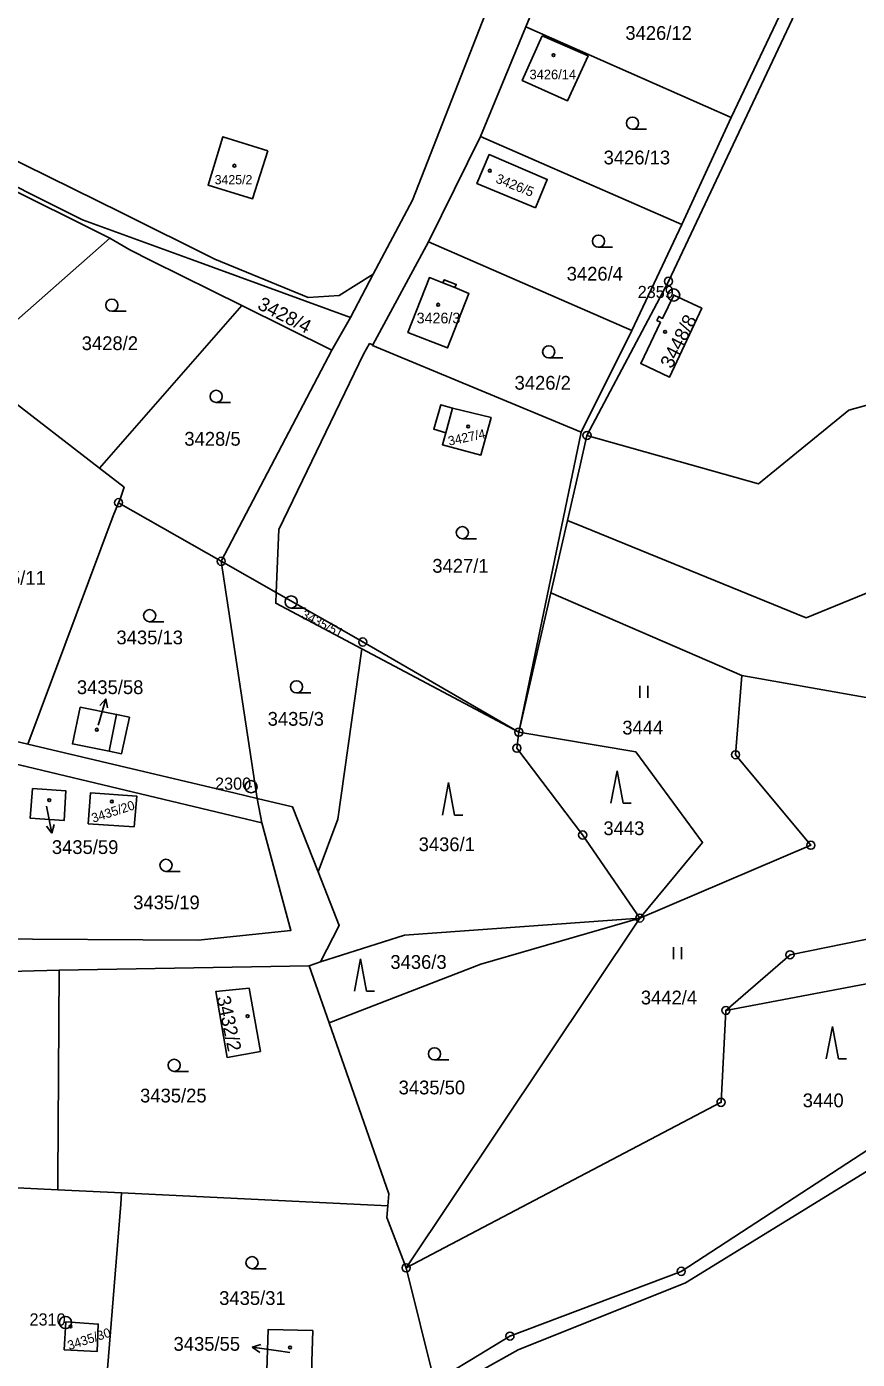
# Model space of a CAD drawing. Extents: x -644096 to -634268, y -1141430 to -1133463.
# Drawn here: x -641809.5 to -641706.9, y -1138397.7 to -1138233.1 of the extents above; entities that cross this region are included whole.
import ezdxf

# ---------------------------------------------------------------- set-up
doc = ezdxf.new("R2010")
doc.units = 0
for name, color, linetype in [('_CIVIL_CONSTRUCTION', 7, 'Continuous'), ('M_Svah_Nasyp', 7, 'Continuous'), ('M_Svah_Zarez', 7, 'Continuous'), ('svrsek_osa_sjezdy', 7, 'Continuous'), ('svrsek_osa_VRT', 7, 'Continuous'), ('svrsek_popisy_VRT', 7, 'Continuous'), ('terminal_VRT', 7, 'Continuous')]:
    doc.layers.add(name, color=color, linetype=linetype)

msp = doc.modelspace()

# ---------------------------------------------------------------- linework, layer by layer
at = {"layer": '_CIVIL_CONSTRUCTION'}
for centre, radius in [((-641730.21, -1138264.55), 0.5), ((-641729.57, -1138266.24), 0.75), ((-641730.21, -1138264.55), 0.0303), ((-641729.57, -1138266.24), 0.03), ((-641740.28, -1138283.58), 0.5), ((-641740.28, -1138283.58), 0.0303), ((-641798.15, -1138291.89), 0.5), ((-641798.15, -1138291.89), 0.0303), ((-641785.47, -1138299.13), 0.5), ((-641785.47, -1138299.13), 0.0303), ((-641767.98, -1138309.09), 0.5), ((-641767.98, -1138309.09), 0.0303), ((-641748.7, -1138320.23), 0.5), ((-641748.7, -1138320.23), 0.0303), ((-641748.94, -1138322.21), 0.5), ((-641748.94, -1138322.21), 0.0303), ((-641721.93, -1138323.02), 0.5), ((-641721.93, -1138323.02), 0.0303), ((-641781.78, -1138326.97), 0.75), ((-641781.78, -1138326.97), 0.03), ((-641740.82, -1138332.93), 0.5), ((-641740.82, -1138332.93), 0.0303), ((-641712.63, -1138334.2), 0.5), ((-641712.63, -1138334.2), 0.0303), ((-641733.76, -1138343.2), 0.5), ((-641733.76, -1138343.2), 0.0303), ((-641715.2, -1138347.73), 0.5), ((-641715.2, -1138347.73), 0.0303), ((-641723.12, -1138354.6), 0.5), ((-641723.12, -1138354.6), 0.0303), ((-641723.72, -1138365.95), 0.5), ((-641723.72, -1138365.95), 0.0303), ((-641762.62, -1138386.4), 0.5), ((-641762.62, -1138386.4), 0.0303), ((-641728.64, -1138386.83), 0.5), ((-641728.64, -1138386.83), 0.0303), ((-641804.7, -1138393.14), 0.75), ((-641804.7, -1138393.14), 0.03), ((-641749.8, -1138394.83), 0.5), ((-641749.8, -1138394.83), 0.0303)]:
    msp.add_circle(centre, radius, dxfattribs=at)
at = {"layer": 'M_Svah_Nasyp'}
for p, q in [((-641758.1, -1138264.74), (-641756.61, -1138265.32)), ((-641757.72, -1138283.24), (-641756.88, -1138280.2)), ((-641798.4, -1138318.04), (-641799.29, -1138322.58))]:
    msp.add_line(p, q, dxfattribs=at)
at = {"layer": 'M_Svah_Zarez'}
for centre in [(-641744.41, -1138236.61), (-641783.84, -1138250.27), (-641752.28, -1138250.88), (-641758.67, -1138267.43), (-641730.64, -1138270.78), (-641754.97, -1138282.47), (-641800.84, -1138319.93), (-641806.71, -1138328.63), (-641798.98, -1138328.8), (-641782.21, -1138355.31), (-641804.09, -1138393.64), (-641776.97, -1138396.23)]:
    msp.add_circle(centre, 0.175, dxfattribs=at)
at = {"layer": 'svrsek_osa_sjezdy'}
for p, q in [((-641734.66, -1138245.76), (-641732.91, -1138245.76)), ((-641738.86, -1138260.34), (-641737.11, -1138260.34)), ((-641798.98, -1138268.25), (-641797.23, -1138268.25)), ((-641745.01, -1138274.01), (-641743.26, -1138274.01)), ((-641786.08, -1138279.51), (-641784.33, -1138279.51)), ((-641755.68, -1138296.34), (-641753.93, -1138296.34)), ((-641776.82, -1138304.9), (-641775.07, -1138304.9)), ((-641794.31, -1138306.59), (-641792.56, -1138306.59)), ((-641733.75, -1138316), (-641733.75, -1138314.5)), ((-641732.75, -1138316), (-641732.75, -1138314.5)), ((-641776.16, -1138315.38), (-641774.41, -1138315.38)), ((-641757.38, -1138326.47), (-641758.13, -1138330.47)), ((-641756.63, -1138330.47), (-641757.38, -1138326.47)), ((-641736.57, -1138325.02), (-641737.32, -1138329.02)), ((-641735.82, -1138329.02), (-641736.57, -1138325.02)), ((-641735.82, -1138329.02), (-641734.82, -1138329.02)), ((-641756.63, -1138330.47), (-641755.63, -1138330.47)), ((-641792.29, -1138337.43), (-641790.54, -1138337.43)), ((-641729.6, -1138348.27), (-641729.6, -1138346.77)), ((-641728.6, -1138348.27), (-641728.6, -1138346.77)), ((-641768.27, -1138348.23), (-641769.02, -1138352.23)), ((-641767.52, -1138352.23), (-641768.27, -1138348.23)), ((-641767.52, -1138352.23), (-641766.52, -1138352.23)), ((-641709.97, -1138356.57), (-641710.72, -1138360.57)), ((-641709.22, -1138360.57), (-641709.97, -1138356.57)), ((-641759.11, -1138360.72), (-641757.36, -1138360.72)), ((-641709.22, -1138360.57), (-641708.22, -1138360.57)), ((-641791.27, -1138362.13), (-641789.52, -1138362.13)), ((-641781.66, -1138386.51), (-641779.91, -1138386.51))]:
    msp.add_line(p, q, dxfattribs=at)
for centre in [(-641734.66, -1138245.01), (-641738.86, -1138259.59), (-641798.98, -1138267.5), (-641745.01, -1138273.26), (-641786.08, -1138278.76), (-641755.68, -1138295.59), (-641776.82, -1138304.15), (-641794.31, -1138305.84), (-641776.16, -1138314.63), (-641792.29, -1138336.68), (-641759.11, -1138359.97), (-641791.27, -1138361.38), (-641781.66, -1138385.76)]:
    msp.add_circle(centre, 0.75, dxfattribs=at)
at = {"layer": 'svrsek_popisy_VRT'}
for p, q in [((-641800.55, -1138319), (-641799.72, -1138316.11)), ((-641799.72, -1138316.11), (-641800.48, -1138316.94)), ((-641799.72, -1138316.11), (-641799.52, -1138317.22)), ((-641800.65, -1138319.36), (-641800.55, -1138319)), ((-641807.04, -1138329.37), (-641806.96, -1138329.77)), ((-641806.96, -1138329.77), (-641806.39, -1138332.72)), ((-641806.39, -1138332.72), (-641807.07, -1138331.83)), ((-641806.39, -1138332.72), (-641806.09, -1138331.64)), ((-641781.63, -1138396.2), (-641780.57, -1138395.85)), ((-641778.66, -1138396.62), (-641781.63, -1138396.2)), ((-641781.63, -1138396.2), (-641780.71, -1138396.84)), ((-641777, -1138396.86), (-641778.66, -1138396.62))]:
    msp.add_line(p, q, dxfattribs=at)
at = {"layer": 'terminal_VRT'}
for p, q in [((-641742.57, -1138220.27), (-641747.83, -1138233.12)), ((-641716.51, -1138231.76), (-641722.46, -1138244.32)), ((-641747.83, -1138233.12), (-641753.43, -1138246.65)), ((-641747.83, -1138233.12), (-641722.46, -1138244.32)), ((-641722.46, -1138244.32), (-641728.56, -1138257.54)), ((-641753.43, -1138246.65), (-641759.87, -1138259.65)), ((-641728.56, -1138257.54), (-641753.43, -1138246.65)), ((-641799.24, -1138259.2), (-641818.53, -1138249.61)), ((-641728.56, -1138257.54), (-641734.75, -1138270.6)), ((-641817.73, -1138275.54), (-641799.24, -1138259.2)), ((-641759.87, -1138259.65), (-641766.74, -1138272.4)), ((-641734.75, -1138270.6), (-641759.87, -1138259.65)), ((-641769.51, -1138269.01), (-641766.68, -1138263.67)), ((-641800.52, -1138287.62), (-641782.94, -1138267.52)), ((-641782.94, -1138267.52), (-641771.82, -1138273.05)), ((-641771.82, -1138273.05), (-641769.51, -1138269.01)), ((-641734.75, -1138270.6), (-641741, -1138283.17)), ((-641785.47, -1138299.13), (-641771.82, -1138273.05)), ((-641812.34, -1138278.47), (-641800.52, -1138287.62)), ((-641741, -1138283.17), (-641748.7, -1138320.23)), ((-641798.15, -1138291.89), (-641785.47, -1138299.13)), ((-641744.75, -1138303.02), (-641742.69, -1138294.07)), ((-641778.68, -1138303), (-641785.47, -1138299.13)), ((-641748.7, -1138320.23), (-641744.75, -1138303.02)), ((-641721.15, -1138313.25), (-641744.75, -1138303.02)), ((-641768.1, -1138309.94), (-641748.7, -1138320.23)), ((-641809.37, -1138321.7), (-641827.1, -1138317.49)), ((-641815.38, -1138323.1), (-641780.43, -1138331.43)), ((-641781.03, -1138328.43), (-641780.43, -1138331.43)), ((-641762.62, -1138386.4), (-641733.76, -1138343.2)), ((-641805.49, -1138349.64), (-641774.62, -1138349.08)), ((-641774.62, -1138349.08), (-641773.19, -1138348.62)), ((-641772.15, -1138356.15), (-641774.62, -1138349.08)), ((-641841.15, -1138350.6), (-641805.49, -1138349.64)), ((-641828.21, -1138375.66), (-641805.66, -1138376.75)), ((-641805.66, -1138376.75), (-641797.77, -1138377.13)), ((-641797.77, -1138377.13), (-641764.9, -1138378.72)), ((-641759.13, -1138400.46), (-641762.62, -1138386.4))]:
    msp.add_line(p, q, dxfattribs=at)
for points in [[(-641740.9, -1138201.05), (-641761.83, -1138254.53), (-641766.68, -1138263.67)], [(-641701.01, -1138202.68), (-641730.21, -1138264.55), (-641740.28, -1138283.58)], [(-641745.81, -1138234.21), (-641740.15, -1138236.71), (-641742.67, -1138242.24), (-641748.27, -1138239.76), (-641745.81, -1138234.21)], [(-641766.68, -1138263.67), (-641770.88, -1138266.3), (-641774.72, -1138266.53), (-641786.27, -1138261.82), (-641797.74, -1138256.08), (-641830.92, -1138239.73), (-641832.34, -1138239.03), (-641834.87, -1138239.21)], [(-641833.06, -1138243.41), (-641831.7, -1138242.36), (-641802.61, -1138256.95), (-641789.02, -1138261.91), (-641769.51, -1138269.01)], [(-641779.7, -1138248.41), (-641785.26, -1138246.68), (-641787.1, -1138252.66), (-641781.6, -1138254.35), (-641779.7, -1138248.41)], [(-641746.66, -1138255.48), (-641753.87, -1138252.48), (-641752.38, -1138248.9), (-641745.19, -1138251.95), (-641746.66, -1138255.48)], [(-641782.94, -1138267.52), (-641794.06, -1138262), (-641796.75, -1138260.67), (-641799.24, -1138259.2)], [(-641740.28, -1138283.58), (-641719.09, -1138289.56), (-641707.92, -1138280.44), (-641699.75, -1138278.19), (-641686.23, -1138278.71), (-641672.58, -1138275.91), (-641665.73, -1138268.46), (-641654.72, -1138262.46), (-641643.02, -1138262.72)], [(-641758.1, -1138264.74), (-641757.91, -1138264.35), (-641756.44, -1138264.92), (-641756.61, -1138265.32), (-641754.87, -1138266.03), (-641757.52, -1138272.78), (-641762.4, -1138270.86), (-641759.74, -1138264.09), (-641758.1, -1138264.74)], [(-641731.18, -1138269.59), (-641733.63, -1138274.69), (-641730.1, -1138276.4), (-641726.11, -1138267.87), (-641729.57, -1138266.24), (-641730.95, -1138269.12), (-641731.42, -1138268.89), (-641731.65, -1138269.37), (-641731.18, -1138269.59)], [(-641638.73, -1138268.6), (-641651.7, -1138278), (-641667.04, -1138291.3), (-641687.63, -1138295.65), (-641713.2, -1138306.13), (-641740.75, -1138294.86), (-641742.69, -1138294.07)], [(-641778.68, -1138303), (-641778.33, -1138295.18), (-641767.89, -1138273.55), (-641767.14, -1138272.23), (-641766.74, -1138272.4)], [(-641766.74, -1138272.4), (-641766.79, -1138272.49), (-641741, -1138283.17)], [(-641757.72, -1138283.24), (-641759.22, -1138282.82), (-641758.33, -1138279.8), (-641756.88, -1138280.2), (-641752.12, -1138281.37), (-641753.39, -1138286), (-641758.14, -1138284.74), (-641757.72, -1138283.24)], [(-641742.69, -1138294.07), (-641741.17, -1138287.48), (-641740.28, -1138283.58)], [(-641800.52, -1138287.62), (-641797.47, -1138289.98), (-641797.96, -1138291.47), (-641798.15, -1138291.89)], [(-641809.37, -1138321.7), (-641798.83, -1138293.52), (-641798.15, -1138291.89)], [(-641785.47, -1138299.13), (-641781.52, -1138325.18), (-641781.03, -1138328.43)], [(-641768.1, -1138309.94), (-641778.73, -1138304.31), (-641778.68, -1138303)], [(-641778.68, -1138303), (-641767.98, -1138309.09), (-641748.7, -1138320.23)], [(-641773.5, -1138337.48), (-641771.05, -1138330.98), (-641768.1, -1138309.94)], [(-641721.15, -1138313.25), (-641721.93, -1138323.02), (-641712.63, -1138334.2), (-641733.76, -1138343.2)], [(-641690.12, -1138316.51), (-641696.47, -1138317.61), (-641721.15, -1138313.25)], [(-641796.78, -1138318.36), (-641797.77, -1138322.89), (-641799.29, -1138322.58), (-641803.86, -1138321.68), (-641802.88, -1138317.16), (-641798.4, -1138318.04), (-641796.78, -1138318.36)], [(-641733.76, -1138343.2), (-641740.82, -1138332.93), (-641748.94, -1138322.21), (-641748.7, -1138320.23)], [(-641733.76, -1138343.2), (-641726.01, -1138333.88), (-641734.26, -1138322.67), (-641748.7, -1138320.23)], [(-641781.03, -1138328.43), (-641783.75, -1138327.78), (-641809.37, -1138321.7)], [(-641808.78, -1138327.19), (-641804.66, -1138327.49), (-641804.87, -1138331.16), (-641809.05, -1138330.87), (-641808.78, -1138327.19)], [(-641796.23, -1138331.91), (-641801.89, -1138331.54), (-641801.61, -1138327.72), (-641795.9, -1138328.13), (-641796.23, -1138331.91)], [(-641773.5, -1138337.48), (-641776.65, -1138329.47), (-641781.03, -1138328.43)], [(-641780.43, -1138331.43), (-641776.86, -1138344.73), (-641788.31, -1138345.91), (-641815.65, -1138345.78)], [(-641684.64, -1138335.2), (-641701.65, -1138344.99), (-641715.2, -1138347.73), (-641723.12, -1138354.6)], [(-641773.19, -1138348.62), (-641770.89, -1138344.11), (-641773.5, -1138337.48)], [(-641615.34, -1138338.9), (-641625.35, -1138344.57), (-641637.86, -1138356.06), (-641681.22, -1138367.23), (-641703.61, -1138373.17), (-641728.11, -1138388.23), (-641748.77, -1138396.54), (-641755.06, -1138400.04), (-641755.45, -1138402.97), (-641756.65, -1138412.09), (-641759.6, -1138424.62), (-641765.78, -1138450.37), (-641748.32, -1138454.34), (-641715.97, -1138456.23), (-641677.07, -1138454.07), (-641654.84, -1138452.11), (-641638.3, -1138451.47), (-641638.71, -1138453.42)], [(-641661.76, -1138357.24), (-641662.88, -1138342.91), (-641675.91, -1138342.88), (-641677.48, -1138339.51), (-641689.63, -1138343.78), (-641702.69, -1138350.73), (-641723.12, -1138354.6)], [(-641773.19, -1138348.62), (-641762.81, -1138345.32), (-641733.76, -1138343.2)], [(-641733.76, -1138343.2), (-641753.38, -1138348.89), (-641772.15, -1138356.15)], [(-641805.66, -1138376.75), (-641805.65, -1138375.37), (-641805.49, -1138349.64)], [(-641780.62, -1138359.66), (-641782.03, -1138351.84), (-641786.13, -1138352.26), (-641784.75, -1138360.41), (-641780.62, -1138359.66)], [(-641764.9, -1138378.72), (-641764.77, -1138377.25), (-641772.15, -1138356.15)], [(-641723.12, -1138354.6), (-641723.72, -1138365.95), (-641762.62, -1138386.4)], [(-641759.13, -1138400.46), (-641754.77, -1138397.83), (-641749.8, -1138394.83), (-641728.64, -1138386.83), (-641704.51, -1138371.13), (-641681.84, -1138365.33), (-641661.76, -1138357.24)], [(-641799.53, -1138398.88), (-641797.88, -1138378.53), (-641797.77, -1138377.13)], [(-641762.62, -1138386.4), (-641765.02, -1138380.19), (-641764.9, -1138378.72)], [(-641804.86, -1138396.51), (-641804.66, -1138393.06), (-641800.65, -1138393.35), (-641800.81, -1138396.75), (-641804.86, -1138396.51)], [(-641774.26, -1138397.96), (-641774.28, -1138399.21), (-641776.29, -1138399.16), (-641779.83, -1138399.06), (-641779.66, -1138394), (-641774.16, -1138394.15), (-641774.26, -1138397.96)]]:
    msp.add_lwpolyline(points, dxfattribs=at)

# ---------------------------------------------------------------- texts
at = {"layer": '_CIVIL_CONSTRUCTION'}
for s, p in [('2359', (-641734.02, -1138266.61)), ('2300', (-641786.23, -1138327.34)), ('2310', (-641809.15, -1138393.52))]:
    msp.add_text(s, height=1.5, dxfattribs=at).set_placement(p)
at = {"layer": 'svrsek_osa_VRT'}
for s, height, p in [('3426/12', 1.7, (-641735.54, -1138234.72)), ('3426/14', 1.19, (-641747.38, -1138239.59)), ('3426/13', 1.7, (-641738.23, -1138250.1)), ('3425/2', 1.14, (-641786.28, -1138252.56)), ('3426/4', 1.7, (-641742.79, -1138264.46)), ('3426/3', 1.32, (-641761.33, -1138269.74)), ('3428/2', 1.7, (-641802.7, -1138273.04)), ('3426/2', 1.7, (-641749.23, -1138277.93)), ('3428/5', 1.7, (-641790.02, -1138284.85)), ('3427/1', 1.7, (-641759.39, -1138300.54)), ('3435/11', 1.7, (-641815.35, -1138302.02)), ('3435/13', 1.7, (-641798.41, -1138309.38)), ('3435/58', 1.7, (-641803.3, -1138315.53)), ('3435/3', 1.7, (-641779.73, -1138319.44)), ('3444', 1.7, (-641735.92, -1138320.52)), ('3443', 1.7, (-641738.25, -1138332.95)), ('3435/59', 1.7, (-641806.39, -1138335.28)), ('3436/1', 1.7, (-641761.08, -1138334.93)), ('3435/19', 1.7, (-641796.34, -1138342.11)), ('3436/3', 1.7, (-641764.57, -1138349.47)), ('3442/4', 1.7, (-641733.63, -1138353.86)), ('3435/25', 1.7, (-641795.49, -1138365.97)), ('3435/50', 1.7, (-641763.55, -1138364.97)), ('3440', 1.7, (-641713.63, -1138366.56)), ('3435/31', 1.7, (-641785.72, -1138390.98)), ('3435/55', 1.7, (-641791.36, -1138396.64))]:
    msp.add_text(s, height=height, dxfattribs=at).set_placement(p)
for s, height, rotation, p in [('3426/5', 1.19, 338, (-641751.66, -1138252.31)), ('3428/4', 1.7, 333, (-641781.11, -1138267.89)), ('3448/8', 1.7, 63, (-641729.81, -1138275.43)), ('3427/4', 1.14, 12, (-641757.31, -1138284.85)), ('3435/51', 1.14, 333, (-641775.67, -1138306.08)), ('3435/20', 1.14, 18, (-641801.28, -1138331.43)), ('3432/2', 1.7, 282, (-641786.05, -1138352.99)), ('3435/30', 1.14, 18, (-641804.24, -1138396.57))]:
    msp.add_text(s, height=height, rotation=rotation, dxfattribs=at).set_placement(p)

doc.saveas('drawing.dxf')
